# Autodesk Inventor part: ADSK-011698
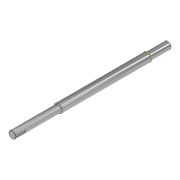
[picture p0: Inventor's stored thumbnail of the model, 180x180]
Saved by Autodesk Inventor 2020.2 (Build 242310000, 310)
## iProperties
Created: 2000-03
Part Number: ADSK-011698
Material: Pearson HRS
Document SubType Name: Modeling
Designer: sspink
Density: 7.83 g/cm^3
Appearance: Métal - Acier
Mass: 1328.56 g
Surface Area: 310.159 cm^2
Volume: 169.675 cm^3
Control State: 0
Master: False
Checked Out: False
Shininess: 0.0
Length Units: 11269
Angle Units: 11279
Time Units: 11290
Mass Units: 11283
Length Display Precision: 3
Angle Display Precision: 2
Compacted: True
Cutlength: 23.25
Material Desc: Material Description goes here
Material_Number: Pearson
Dimensions: 24x432x24 mm
Mass: 1,329 kg
VLT_Material: Pearson HRS
Density: 0.0
Volumn: 0.0
Area: 0.0
PropertySet Name: Model Information
Author: sspink
Revision Number: -
Title: ADSK-011698
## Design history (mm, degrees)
node "Solide1"
  node "Extrusion1" dims "d1" = 432, "d2" = 0
  node "Extrusion2" dims "d6" = 25, "d7" = 0
sketch "Sketch1"
  geometry: C1 r 10 at (0, 0); 1 further point
  constraints: 1 centre point, 1 coincident
  dimensions: "d0" = 20 diameter of C1
sketch "Sketch2"
  geometry: L1 (0, 0)-(0, 8); L2 (0, 8)-(2.5, 8); L3 (2.5, 8)-(2.5, 9.682); L4 (0, 8)-(-2.5, 8); L5 (-2.5, 8)-(-2.5, 9.682); A1 r 10 centre (0, 0) between (2.5, 9.682) and (-2.5, 9.682) reference
  constraints: 10 end point, 4 perpendicular, 2 point on circle, 1 vertical
  dimensions: "d3" = 5 distance between parallel lines of L3 L5; "d4" = 2.5 distance between parallel lines of L1 L3 (= 0.5 x d3); "d5" = 8 distance from line of L1.start L4
sketch "Skizze4"
  geometry: C1 r 12 at (0, 0); 1 further point
  constraints: 1 centre point, 1 coincident
  dimensions: "d16" = 24 diameter of C1
extrude "Extrusion4" join sketch "Skizze4" distance "d17" = 250; taper "d18" = 0 deg
chamfer "Fase2" distance "d19" = 2; stored, may be unused: second distance "d20" = 2, angle "d21" = 45 deg
feature "Gewinde1" dims "d22" = 246, "d23" = 0
fillet "Rundung1"
chamfer "Fase1" distance "d8" = 1; stored, may be unused: second distance "d9" = 2, angle "d10" = 45 deg
workplane "Arbeitsebene1"
sketch "Skizze3"
  geometry: L1 (-9, 216)-(9, 216) reference; L2 (2.5, 216)-(2.5, 191); L3 (-2.5, 191)-(-2.5, 216); A1 r 2.5 centre (0, 191) between (-2.5, 191) and (2.5, 191); 2 further points
  constraints: 4 end point, 2 point on circle, 2 point on line, 2 tangent, 1 centre point, 1 midpoint, 1 perpendicular, 1 vertical, 1 vertical alignment
  dimensions: "d11" = 5 distance between parallel lines of L3 L2; "d12" = 25 distance of L3.start L3.end
extrude "Extrusion3" cut sketch "Skizze3" distance "d13" = 2; taper "d14" = 0 deg
workplane "Arbeitsebene2"
node "Corps solides"
node "Corps surfaciques"
